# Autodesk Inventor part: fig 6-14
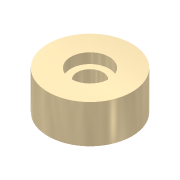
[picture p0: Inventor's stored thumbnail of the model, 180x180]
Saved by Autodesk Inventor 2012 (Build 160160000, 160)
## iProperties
Shininess: 65.0
Angle Display Precision: 2
Document Length Units: 11269
Document Angle Units: 11279
Document Time Units: 11290
Document Mass Units: 11283
Document Length Units Precision: 3
Document Angle Units Precision: 2
Created: 2001-11
Part Number: fig 6-14
Document SubType Name: Modeling
Designer: Renu Muthoo
Density: 1 g/cm^3
Material: Default
Density: 0.0
Volumn: 0.0
Area: 0.0
PropertySet Name: Model Information
Control State: 0
Master: False
Checked Out: False
Author: Renu Muthoo
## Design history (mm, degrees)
sketch "Sketch1"
  geometry: C1 r 16.401 at (0, 0)
  constraints: 1 centre point
extrude "Extrusion1" new body sketch "Sketch1" distance "d0" = 15; taper "d1" = 0 deg
hole "Hole3" diameter "d18" = 10.106; stored, may be unused: countersink angle "d22" = 90 deg, drill point angle "d24" = 118 deg; dims "d16" = 10, "d17" = 10, "d19" = 6, "d20" = 15, "d21" = 4, "d23" = 10
body "Solid1"
